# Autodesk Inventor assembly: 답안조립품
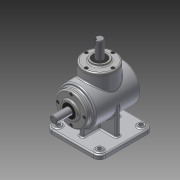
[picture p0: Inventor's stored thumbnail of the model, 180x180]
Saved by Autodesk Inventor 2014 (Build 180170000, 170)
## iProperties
Created: 2015-07
Part Number: 답안조립품
Document SubType Name: Assembly
Designer: basic
Author: basic
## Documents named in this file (14)
- C:\Users\basic\Desktop\450705V1007\답안조립품.iam
- C:\Users\basic\Desktop\450705V1007\본체.ipt
- C:\Users\basic\Desktop\450705V1007\M4.ipt
- C:\Users\basic\Desktop\450705V1007\메인 베벨기어.ipt
- C:\Users\basic\Desktop\450705V1007\메인 축.ipt
- 메인 축.ipt
- C:\Users\basic\Desktop\450705V1007\베어링 6203.ipt
- C:\Users\basic\Desktop\450705V1007\서브 베벨기어.ipt
- C:\Users\basic\Desktop\450705V1007\서브 축.ipt
- 서브 축.ipt
- C:\Users\basic\Desktop\450705V1007\오일실.ipt
- C:\Users\basic\Desktop\450705V1007\커버.ipt
- C:\Users\basic\Desktop\450705V1007\키 4x4.ipt
- C:\Users\basic\Desktop\450705V1007\키 5x5.ipt
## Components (8 placed, 1 different names)
1. M4:1
2. M4:2
3. M4:3
4. M4:4
5. M4:5
6. M4:6
7. M4:7
8. M4:8
